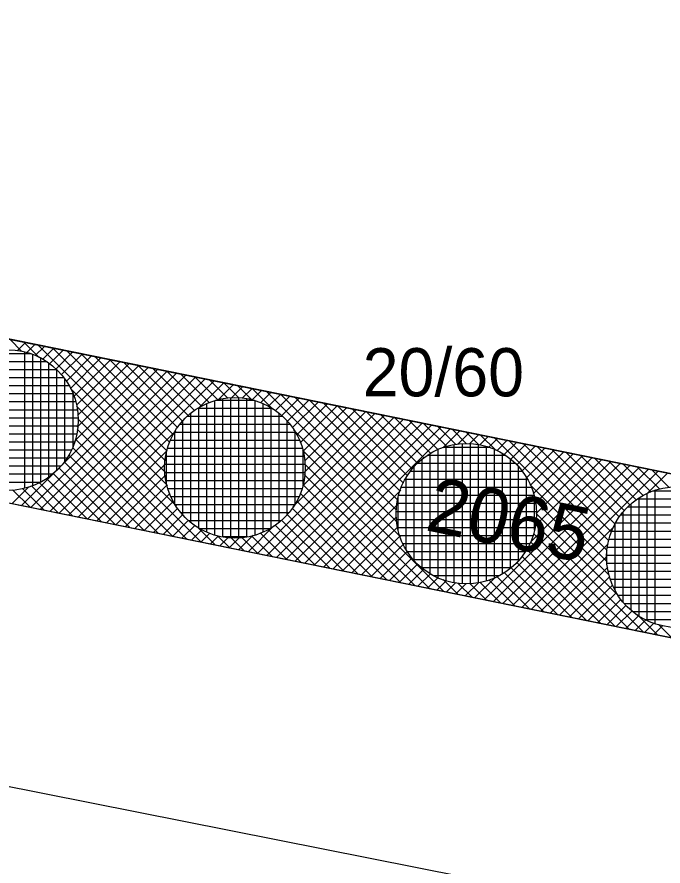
# Model space of a CAD drawing. Extents: x -566461 to -565198, y -1096301 to -1095707.
# Drawn here: x -565811.47 to -565795.4, y -1096125.98 to -1096104.85 of the extents above; entities that cross this region are included whole.
import ezdxf

# ---------------------------------------------------------------- set-up
doc = ezdxf.new("R2010")
doc.units = 0
for name, color, linetype in [('Vrstva 1', 7, 'Continuous'), ('Vrstva 18', 7, 'Continuous'), ('Vrstva 40', 7, 'Continuous'), ('Vrstva 41', 7, 'Continuous'), ('Vrstva 42', 7, 'Continuous'), ('Vrstva 44', 7, 'Continuous')]:
    doc.layers.add(name, color=color, linetype=linetype)

msp = doc.modelspace()

# ---------------------------------------------------------------- linework, layer by layer
at = {"layer": 'Vrstva 1'}
for p, q in [((-565849.04, -1096105.26), (-565748.22, -1096125.78)), ((-565697.28, -1096140.23), (-565854, -1096108.33)), ((-565855.22, -1096115.35), (-565699.29, -1096146.31))]:
    msp.add_line(p, q, dxfattribs=at)
at = {"layer": 'Vrstva 41'}
for p, q in [((-565811.656, -1096112.869), (-565811.352, -1096113.173)), ((-565811.47, -1096113.154), (-565811.264, -1096112.949)), ((-565811.301, -1096112.942), (-565810.915, -1096113.327)), ((-565811.235, -1096113.203), (-565811.029, -1096112.997)), ((-565811.025, -1096113.275), (-565810.794, -1096113.045)), ((-565810.945, -1096113.014), (-565807.785, -1096116.175)), ((-565810.835, -1096113.368), (-565810.559, -1096113.092)), ((-565810.59, -1096113.086), (-565807.781, -1096115.895)), ((-565810.664, -1096113.48), (-565810.324, -1096113.14)), ((-565810.51, -1096113.609), (-565810.089, -1096113.188)), ((-565810.373, -1096113.754), (-565809.854, -1096113.236)), ((-565810.251, -1096113.916), (-565809.619, -1096113.284)), ((-565810.235, -1096113.158), (-565807.738, -1096115.656)), ((-565809.88, -1096113.231), (-565807.67, -1096115.441)), ((-565809.525, -1096113.303), (-565807.581, -1096115.247)), ((-565810.147, -1096114.094), (-565809.384, -1096113.332)), ((-565810.062, -1096114.292), (-565809.149, -1096113.379)), ((-565809.997, -1096114.51), (-565808.914, -1096113.427)), ((-565809.975, -1096115.054), (-565808.444, -1096113.523)), ((-565809.964, -1096114.759), (-565808.679, -1096113.475)), ((-565809.17, -1096113.375), (-565807.474, -1096115.071)), ((-565808.815, -1096113.448), (-565807.349, -1096114.913)), ((-565808.46, -1096113.52), (-565807.208, -1096114.771)), ((-565811.364, -1096117.008), (-565807.974, -1096113.619)), ((-565811.129, -1096117.056), (-565807.739, -1096113.666)), ((-565810.894, -1096117.104), (-565807.504, -1096113.714)), ((-565810.038, -1096115.399), (-565808.209, -1096113.571)), ((-565808.104, -1096113.592), (-565807.05, -1096114.647)), ((-565807.749, -1096113.664), (-565806.874, -1096114.54)), ((-565810.659, -1096117.152), (-565807.269, -1096113.762)), ((-565810.424, -1096117.2), (-565807.034, -1096113.81)), ((-565810.189, -1096117.248), (-565806.799, -1096113.858)), ((-565809.954, -1096117.295), (-565806.564, -1096113.906)), ((-565807.394, -1096113.737), (-565806.681, -1096114.45)), ((-565807.039, -1096113.809), (-565806.466, -1096114.382)), ((-565806.684, -1096113.881), (-565806.226, -1096114.339)), ((-565810.147, -1096114.095), (-565807.731, -1096116.511)), ((-565806.973, -1096114.597), (-565806.329, -1096113.953)), ((-565806.479, -1096114.386), (-565806.094, -1096114.001)), ((-565806.329, -1096113.954), (-565805.947, -1096114.335)), ((-565806.145, -1096114.335), (-565805.859, -1096114.049)), ((-565805.974, -1096114.026), (-565805.611, -1096114.389)), ((-565805.866, -1096114.339), (-565805.624, -1096114.097)), ((-565805.628, -1096114.384), (-565805.389, -1096114.145)), ((-565805.619, -1096114.098), (-565805.105, -1096114.611)), ((-565805.414, -1096114.452), (-565805.154, -1096114.193)), ((-565805.263, -1096114.17), (-565802.016, -1096117.418)), ((-565805.221, -1096114.542), (-565804.919, -1096114.24)), ((-565805.046, -1096114.65), (-565804.684, -1096114.288)), ((-565804.908, -1096114.243), (-565802.025, -1096117.126)), ((-565804.888, -1096114.775), (-565804.449, -1096114.336)), ((-565804.553, -1096114.315), (-565801.996, -1096116.872)), ((-565809.993, -1096114.532), (-565807.506, -1096117.019)), ((-565804.747, -1096114.917), (-565804.214, -1096114.384)), ((-565804.623, -1096115.076), (-565803.979, -1096114.432)), ((-565804.516, -1096115.252), (-565803.744, -1096114.48)), ((-565804.428, -1096115.446), (-565803.509, -1096114.527)), ((-565804.36, -1096115.662), (-565803.274, -1096114.575)), ((-565804.198, -1096114.387), (-565801.936, -1096116.649)), ((-565803.843, -1096114.46), (-565801.853, -1096116.449)), ((-565803.488, -1096114.532), (-565801.751, -1096116.269)), ((-565804.608, -1096117.041), (-565802.334, -1096114.767)), ((-565804.372, -1096116.522), (-565802.569, -1096114.719)), ((-565804.323, -1096116.189), (-565802.804, -1096114.671)), ((-565804.318, -1096115.902), (-565803.039, -1096114.623)), ((-565803.133, -1096114.604), (-565801.631, -1096116.105)), ((-565802.778, -1096114.676), (-565801.495, -1096115.958)), ((-565802.422, -1096114.749), (-565801.344, -1096115.827)), ((-565809.959, -1096114.849), (-565806.888, -1096117.919)), ((-565805.489, -1096118.204), (-565802.099, -1096114.814)), ((-565805.254, -1096118.252), (-565801.864, -1096114.862)), ((-565805.019, -1096118.3), (-565801.629, -1096114.91)), ((-565804.784, -1096118.348), (-565801.394, -1096114.958)), ((-565802.067, -1096114.821), (-565801.175, -1096115.713)), ((-565801.712, -1096114.893), (-565800.989, -1096115.617)), ((-565801.357, -1096114.966), (-565800.78, -1096115.542)), ((-565809.981, -1096115.11), (-565807.244, -1096117.847)), ((-565809.719, -1096117.343), (-565807.523, -1096115.147)), ((-565804.591, -1096115.125), (-565801.93, -1096117.786)), ((-565804.549, -1096118.396), (-565801.159, -1096115.006)), ((-565804.314, -1096118.443), (-565800.924, -1096115.054)), ((-565804.079, -1096118.491), (-565800.689, -1096115.101)), ((-565801.002, -1096115.038), (-565800.548, -1096115.492)), ((-565800.879, -1096115.575), (-565800.454, -1096115.149)), ((-565800.647, -1096115.11), (-565800.287, -1096115.47)), ((-565800.507, -1096115.485), (-565800.219, -1096115.197)), ((-565800.292, -1096115.182), (-565799.973, -1096115.501)), ((-565810.024, -1096115.349), (-565807.599, -1096117.775)), ((-565800.213, -1096115.474), (-565799.984, -1096115.245)), ((-565799.959, -1096115.503), (-565799.749, -1096115.293)), ((-565799.937, -1096115.255), (-565799.56, -1096115.631)), ((-565799.735, -1096115.562), (-565799.514, -1096115.341)), ((-565799.581, -1096115.327), (-565796.783, -1096118.126)), ((-565799.535, -1096115.644), (-565799.279, -1096115.388)), ((-565799.226, -1096115.399), (-565796.741, -1096117.884)), ((-565810.097, -1096115.56), (-565807.954, -1096117.703)), ((-565804.369, -1096115.631), (-565800.851, -1096119.148)), ((-565799.354, -1096115.746), (-565799.044, -1096115.436)), ((-565799.19, -1096115.865), (-565798.809, -1096115.484)), ((-565799.042, -1096116.001), (-565798.574, -1096115.532)), ((-565798.911, -1096116.152), (-565798.339, -1096115.58)), ((-565798.871, -1096115.471), (-565796.674, -1096117.669)), ((-565798.796, -1096116.32), (-565798.104, -1096115.628)), ((-565798.516, -1096115.544), (-565796.586, -1096117.474)), ((-565798.161, -1096115.616), (-565796.479, -1096117.298)), ((-565810.19, -1096115.749), (-565808.309, -1096117.63)), ((-565809.484, -1096117.391), (-565807.734, -1096115.641)), ((-565798.699, -1096116.505), (-565797.869, -1096115.675)), ((-565798.624, -1096116.713), (-565797.634, -1096115.723)), ((-565798.573, -1096116.945), (-565797.399, -1096115.771)), ((-565798.55, -1096117.205), (-565797.164, -1096115.819)), ((-565797.806, -1096115.688), (-565796.355, -1096117.139)), ((-565797.451, -1096115.761), (-565796.215, -1096116.996)), ((-565797.096, -1096115.833), (-565796.058, -1096116.871)), ((-565810.303, -1096115.92), (-565808.664, -1096117.558)), ((-565809.249, -1096117.439), (-565807.785, -1096115.975)), ((-565804.315, -1096115.967), (-565801.206, -1096119.076)), ((-565799.849, -1096119.352), (-565796.459, -1096115.963)), ((-565799.614, -1096119.4), (-565796.224, -1096116.01)), ((-565799.379, -1096119.448), (-565795.989, -1096116.058)), ((-565798.703, -1096117.924), (-565796.694, -1096115.915)), ((-565798.583, -1096117.521), (-565796.929, -1096115.867)), ((-565796.74, -1096115.905), (-565795.883, -1096116.763)), ((-565796.385, -1096115.977), (-565795.69, -1096116.673)), ((-565796.03, -1096116.05), (-565795.476, -1096116.604)), ((-565810.578, -1096116.21), (-565809.374, -1096117.413)), ((-565810.432, -1096116.073), (-565809.019, -1096117.486)), ((-565809.014, -1096117.487), (-565807.781, -1096116.254)), ((-565804.328, -1096116.238), (-565801.561, -1096119.004)), ((-565799.144, -1096119.496), (-565795.754, -1096116.106)), ((-565798.909, -1096119.544), (-565795.519, -1096116.154)), ((-565795.805, -1096116.723), (-565795.284, -1096116.202)), ((-565795.675, -1096116.122), (-565795.238, -1096116.559)), ((-565810.919, -1096116.435), (-565810.085, -1096117.269)), ((-565810.74, -1096116.331), (-565809.729, -1096117.341)), ((-565798.711, -1096116.48), (-565796.785, -1096118.406)), ((-565811.599, -1096116.961), (-565811.181, -1096116.542)), ((-565811.585, -1096116.617), (-565811.15, -1096117.052)), ((-565811.335, -1096116.584), (-565810.795, -1096117.124)), ((-565811.116, -1096116.52), (-565810.44, -1096117.197)), ((-565808.779, -1096117.535), (-565807.736, -1096116.492)), ((-565804.362, -1096116.486), (-565801.917, -1096118.931)), ((-565803.844, -1096118.539), (-565801.925, -1096116.621)), ((-565808.544, -1096117.582), (-565807.668, -1096116.706)), ((-565808.309, -1096117.63), (-565807.578, -1096116.899)), ((-565804.52, -1096116.894), (-565802.627, -1096118.787)), ((-565804.43, -1096116.701), (-565802.272, -1096118.859)), ((-565798.581, -1096116.893), (-565796.728, -1096118.746)), ((-565808.074, -1096117.678), (-565807.47, -1096117.074)), ((-565804.627, -1096117.07), (-565802.982, -1096118.715)), ((-565803.609, -1096118.587), (-565802.014, -1096116.993)), ((-565807.839, -1096117.726), (-565807.345, -1096117.232)), ((-565804.751, -1096117.228), (-565803.337, -1096118.642)), ((-565803.374, -1096118.635), (-565802.026, -1096117.287)), ((-565798.55, -1096117.207), (-565796.489, -1096119.268)), ((-565807.604, -1096117.774), (-565807.203, -1096117.373)), ((-565807.369, -1096117.822), (-565807.044, -1096117.497)), ((-565806.999, -1096117.526), (-565806.533, -1096117.992)), ((-565805.724, -1096118.156), (-565805.079, -1096117.512)), ((-565805.051, -1096117.494), (-565804.047, -1096118.498)), ((-565804.893, -1096117.369), (-565803.692, -1096118.57)), ((-565798.674, -1096119.592), (-565796.617, -1096117.535)), ((-565798.577, -1096117.463), (-565795.879, -1096120.16)), ((-565807.134, -1096117.869), (-565806.868, -1096117.604)), ((-565806.899, -1096117.917), (-565806.674, -1096117.692)), ((-565805.959, -1096118.109), (-565805.598, -1096117.748)), ((-565805.421, -1096117.69), (-565804.758, -1096118.353)), ((-565805.227, -1096117.601), (-565804.403, -1096118.425)), ((-565803.139, -1096118.683), (-565801.997, -1096117.541)), ((-565798.622, -1096117.7), (-565796.235, -1096120.088)), ((-565806.664, -1096117.965), (-565806.458, -1096117.76)), ((-565806.491, -1096117.751), (-565806.178, -1096118.064)), ((-565806.429, -1096118.013), (-565806.218, -1096117.802)), ((-565806.194, -1096118.061), (-565805.938, -1096117.804)), ((-565806.155, -1096117.805), (-565805.823, -1096118.136)), ((-565805.875, -1096117.801), (-565805.468, -1096118.209)), ((-565805.636, -1096117.758), (-565805.113, -1096118.281)), ((-565802.904, -1096118.731), (-565801.938, -1096117.765)), ((-565798.697, -1096117.909), (-565796.59, -1096120.016)), ((-565798.439, -1096119.639), (-565796.758, -1096117.959)), ((-565802.669, -1096118.778), (-565801.856, -1096117.965)), ((-565802.434, -1096118.826), (-565801.754, -1096118.146)), ((-565798.793, -1096118.095), (-565796.945, -1096119.943)), ((-565802.199, -1096118.874), (-565801.635, -1096118.31)), ((-565798.907, -1096118.264), (-565797.3, -1096119.871)), ((-565798.204, -1096119.687), (-565796.79, -1096118.274)), ((-565801.964, -1096118.922), (-565801.499, -1096118.458)), ((-565801.729, -1096118.97), (-565801.348, -1096118.589)), ((-565799.185, -1096118.551), (-565798.01, -1096119.727)), ((-565799.038, -1096118.415), (-565797.655, -1096119.799)), ((-565797.969, -1096119.735), (-565796.771, -1096118.538)), ((-565801.494, -1096119.018), (-565801.18, -1096118.704)), ((-565801.259, -1096119.065), (-565800.995, -1096118.801)), ((-565800.084, -1096119.305), (-565799.576, -1096118.797)), ((-565799.529, -1096118.773), (-565798.72, -1096119.582)), ((-565799.349, -1096118.671), (-565798.365, -1096119.654)), ((-565797.734, -1096119.783), (-565796.721, -1096118.771)), ((-565801.024, -1096119.113), (-565800.787, -1096118.876)), ((-565800.866, -1096118.85), (-565800.496, -1096119.221)), ((-565800.789, -1096119.161), (-565800.555, -1096118.927)), ((-565800.554, -1096119.209), (-565800.295, -1096118.95)), ((-565800.498, -1096118.936), (-565800.141, -1096119.293)), ((-565800.319, -1096119.257), (-565799.983, -1096118.92)), ((-565800.206, -1096118.945), (-565799.786, -1096119.365)), ((-565799.952, -1096118.916), (-565799.431, -1096119.437)), ((-565799.729, -1096118.856), (-565799.076, -1096119.51)), ((-565797.499, -1096119.831), (-565796.648, -1096118.98)), ((-565797.264, -1096119.879), (-565796.553, -1096119.168)), ((-565797.029, -1096119.926), (-565796.44, -1096119.338)), ((-565796.794, -1096119.974), (-565796.309, -1096119.49)), ((-565796.559, -1096120.022), (-565796.163, -1096119.626)), ((-565796.324, -1096120.07), (-565796, -1096119.747)), ((-565796.089, -1096120.118), (-565795.82, -1096119.849)), ((-565796.028, -1096119.729), (-565795.524, -1096120.233)), ((-565795.854, -1096120.166), (-565795.621, -1096119.933)), ((-565795.619, -1096120.213), (-565795.4, -1096119.995)), ((-565795.506, -1096119.968), (-565795.169, -1096120.305))]:
    msp.add_line(p, q, dxfattribs=at)
at = {"layer": 'Vrstva 42'}
msp.add_lwpolyline([(-565828.2, -1096027.12), (-565826.72, -1096023.51), (-565829.55, -1096025.32), (-565832.07, -1096026.09), (-565854, -1096108.33), (-565697.28, -1096140.23), (-565696.05, -1096136.4), (-565849.04, -1096105.26)], close=True, dxfattribs=at)
at = {"layer": 'Vrstva 44'}
for p, q in [((-565811.123, -1096113.23), (-565812.278, -1096113.23)), ((-565811.28, -1096116.578), (-565811.28, -1096113.183)), ((-565811.08, -1096116.516), (-565811.08, -1096113.245)), ((-565810.721, -1096113.43), (-565812.677, -1096113.43)), ((-565810.88, -1096116.424), (-565810.88, -1096113.334)), ((-565810.68, -1096116.3), (-565810.68, -1096113.46)), ((-565810.476, -1096113.63), (-565812.923, -1096113.63)), ((-565810.48, -1096116.132), (-565810.48, -1096113.626)), ((-565810.302, -1096113.83), (-565813.099, -1096113.83)), ((-565810.28, -1096115.901), (-565810.28, -1096113.86)), ((-565810.171, -1096114.03), (-565813.228, -1096114.03)), ((-565810.077, -1096114.23), (-565813.323, -1096114.23)), ((-565810.08, -1096115.537), (-565810.08, -1096114.222)), ((-565806.35, -1096117.792), (-565806.35, -1096114.346)), ((-565806.15, -1096117.815), (-565806.15, -1096114.324)), ((-565805.95, -1096117.816), (-565805.95, -1096114.325)), ((-565805.75, -1096117.793), (-565805.75, -1096114.348)), ((-565810.011, -1096114.43), (-565813.39, -1096114.43)), ((-565806.95, -1096117.569), (-565806.95, -1096114.571)), ((-565806.75, -1096117.672), (-565806.75, -1096114.468)), ((-565806.55, -1096117.747), (-565806.55, -1096114.394)), ((-565805.565, -1096114.39), (-565806.537, -1096114.39)), ((-565805.55, -1096117.745), (-565805.55, -1096114.394)), ((-565805.35, -1096117.672), (-565805.35, -1096114.467)), ((-565805.15, -1096117.57), (-565805.15, -1096114.571)), ((-565809.969, -1096114.63), (-565813.431, -1096114.63)), ((-565804.859, -1096114.79), (-565807.243, -1096114.79)), ((-565807.15, -1096117.43), (-565807.15, -1096114.711)), ((-565805.119, -1096114.59), (-565806.983, -1096114.59)), ((-565804.95, -1096117.429), (-565804.95, -1096114.709)), ((-565809.951, -1096114.83), (-565813.448, -1096114.83)), ((-565804.675, -1096114.99), (-565807.425, -1096114.99)), ((-565807.35, -1096117.239), (-565807.35, -1096114.899)), ((-565804.75, -1096117.241), (-565804.75, -1096114.901)), ((-565809.958, -1096115.03), (-565813.442, -1096115.03)), ((-565804.539, -1096115.19), (-565807.562, -1096115.19)), ((-565807.55, -1096116.969), (-565807.55, -1096115.17)), ((-565804.55, -1096116.97), (-565804.55, -1096115.172)), ((-565809.987, -1096115.23), (-565813.413, -1096115.23)), ((-565804.438, -1096115.39), (-565807.66, -1096115.39)), ((-565810.041, -1096115.43), (-565813.361, -1096115.43)), ((-565810.12, -1096115.63), (-565813.28, -1096115.63)), ((-565804.369, -1096115.59), (-565807.731, -1096115.59)), ((-565800.99, -1096118.812), (-565800.99, -1096115.608)), ((-565799.713, -1096115.56), (-565800.868, -1096115.56)), ((-565800.79, -1096118.887), (-565800.79, -1096115.534)), ((-565800.59, -1096118.932), (-565800.59, -1096115.486)), ((-565800.39, -1096118.955), (-565800.39, -1096115.464)), ((-565800.19, -1096118.956), (-565800.19, -1096115.465)), ((-565799.99, -1096118.933), (-565799.99, -1096115.488)), ((-565799.79, -1096118.885), (-565799.79, -1096115.534)), ((-565799.59, -1096118.812), (-565799.59, -1096115.607)), ((-565810.232, -1096115.83), (-565813.167, -1096115.83)), ((-565804.324, -1096115.79), (-565807.777, -1096115.79)), ((-565807.75, -1096116.483), (-565807.75, -1096115.657)), ((-565804.35, -1096116.479), (-565804.35, -1096115.66)), ((-565799.311, -1096115.76), (-565801.267, -1096115.76)), ((-565801.19, -1096118.709), (-565801.19, -1096115.711)), ((-565799.39, -1096118.71), (-565799.39, -1096115.711)), ((-565810.383, -1096116.03), (-565813.018, -1096116.03)), ((-565804.303, -1096115.99), (-565807.797, -1096115.99)), ((-565801.59, -1096118.379), (-565801.59, -1096116.039)), ((-565799.066, -1096115.96), (-565801.513, -1096115.96)), ((-565801.39, -1096118.57), (-565801.39, -1096115.851)), ((-565799.19, -1096118.569), (-565799.19, -1096115.849)), ((-565798.99, -1096118.381), (-565798.99, -1096116.041)), ((-565810.59, -1096116.23), (-565812.812, -1096116.23)), ((-565804.304, -1096116.19), (-565807.794, -1096116.19)), ((-565798.892, -1096116.16), (-565801.689, -1096116.16)), ((-565810.891, -1096116.43), (-565812.512, -1096116.43)), ((-565804.331, -1096116.39), (-565807.768, -1096116.39)), ((-565798.761, -1096116.36), (-565801.818, -1096116.36)), ((-565801.79, -1096118.109), (-565801.79, -1096116.31)), ((-565798.79, -1096118.11), (-565798.79, -1096116.312)), ((-565804.381, -1096116.59), (-565807.719, -1096116.59)), ((-565798.667, -1096116.56), (-565801.913, -1096116.56)), ((-565794.445, -1096116.65), (-565795.658, -1096116.65)), ((-565795.59, -1096119.953), (-565795.59, -1096116.627)), ((-565804.457, -1096116.79), (-565807.645, -1096116.79)), ((-565801.99, -1096117.623), (-565801.99, -1096116.797)), ((-565798.601, -1096116.76), (-565801.98, -1096116.76)), ((-565798.59, -1096117.619), (-565798.59, -1096116.8)), ((-565794.057, -1096116.85), (-565796.041, -1096116.85)), ((-565795.99, -1096119.766), (-565795.99, -1096116.815)), ((-565795.79, -1096119.874), (-565795.79, -1096116.706)), ((-565804.562, -1096116.99), (-565807.536, -1096116.99)), ((-565798.559, -1096116.96), (-565802.021, -1096116.96)), ((-565793.816, -1096117.05), (-565796.282, -1096117.05)), ((-565796.19, -1096119.615), (-565796.19, -1096116.965)), ((-565804.708, -1096117.19), (-565807.393, -1096117.19)), ((-565798.541, -1096117.16), (-565802.038, -1096117.16)), ((-565793.645, -1096117.25), (-565796.457, -1096117.25)), ((-565796.39, -1096119.414), (-565796.39, -1096117.167)), ((-565804.903, -1096117.39), (-565807.196, -1096117.39)), ((-565798.548, -1096117.36), (-565802.032, -1096117.36)), ((-565796.59, -1096119.118), (-565796.59, -1096117.463)), ((-565793.515, -1096117.45), (-565796.583, -1096117.45)), ((-565805.186, -1096117.59), (-565806.913, -1096117.59)), ((-565798.577, -1096117.56), (-565802.003, -1096117.56)), ((-565793.423, -1096117.65), (-565796.677, -1096117.65)), ((-565805.734, -1096117.79), (-565806.362, -1096117.79)), ((-565798.631, -1096117.76), (-565801.951, -1096117.76)), ((-565798.71, -1096117.96), (-565801.87, -1096117.96)), ((-565793.358, -1096117.85), (-565796.743, -1096117.85)), ((-565798.822, -1096118.16), (-565801.757, -1096118.16)), ((-565796.79, -1096118.458), (-565796.79, -1096118.123)), ((-565793.318, -1096118.05), (-565796.783, -1096118.05)), ((-565798.973, -1096118.36), (-565801.608, -1096118.36)), ((-565793.301, -1096118.25), (-565796.798, -1096118.25)), ((-565799.18, -1096118.56), (-565801.402, -1096118.56)), ((-565793.309, -1096118.45), (-565796.791, -1096118.45)), ((-565799.481, -1096118.76), (-565801.102, -1096118.76)), ((-565793.339, -1096118.65), (-565796.761, -1096118.65)), ((-565793.394, -1096118.85), (-565796.708, -1096118.85)), ((-565793.474, -1096119.05), (-565796.625, -1096119.05)), ((-565793.589, -1096119.25), (-565796.511, -1096119.25)), ((-565793.741, -1096119.45), (-565796.359, -1096119.45)), ((-565793.952, -1096119.65), (-565796.15, -1096119.65)), ((-565794.26, -1096119.85), (-565795.842, -1096119.85))]:
    msp.add_line(p, q, dxfattribs=at)
for centre in [(-565811.7, -1096114.88), (-565806.05, -1096116.07), (-565800.29, -1096117.21), (-565795.05, -1096118.29)]:
    msp.add_circle(centre, 1.75, dxfattribs=at)

# ---------------------------------------------------------------- texts
at = {"layer": 'Vrstva 18'}
msp.add_text('2065', height=1.36, rotation=348.3, dxfattribs=at).set_placement((-565801.344, -1096117.614))
at = {"layer": 'Vrstva 40'}
msp.add_text('20/60', height=1.2, dxfattribs=at).set_placement((-565802.87, -1096114.29))

doc.saveas('drawing.dxf')
